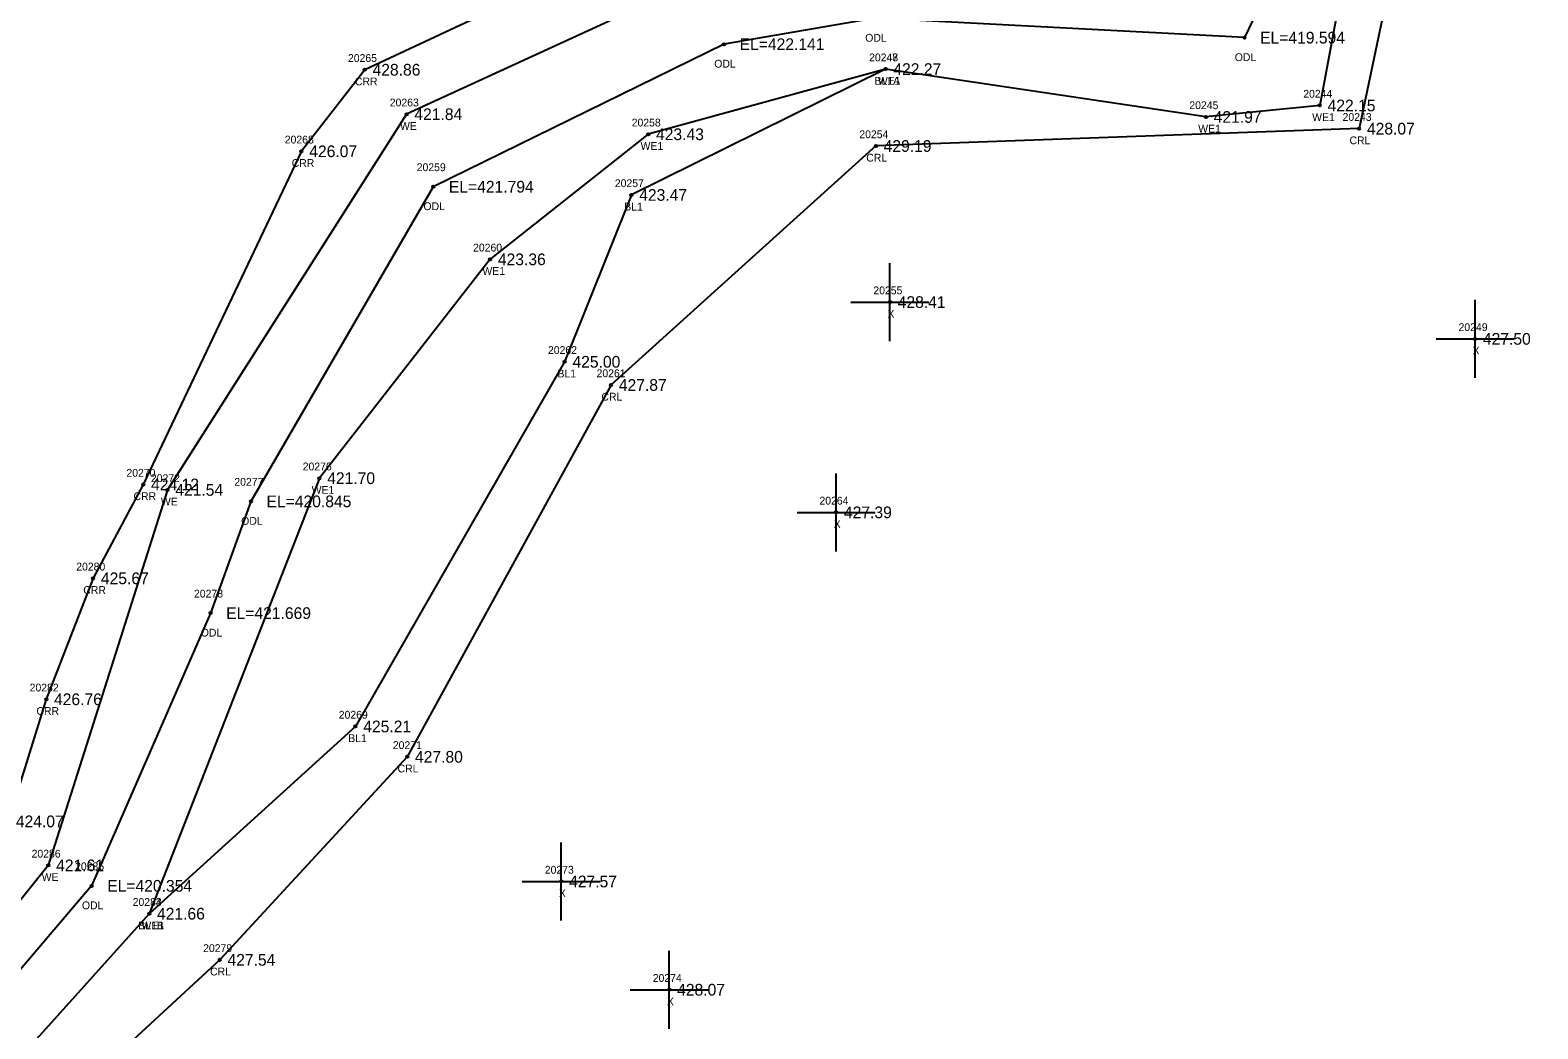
# Model space of a CAD drawing. Extents: x 1858461 to 1858936, y 1147060 to 1148183.
# Drawn here: x 1858716.7 to 1858909.9, y 1147619.9 to 1147747.9 of the extents above; entities that cross this region are included whole.
import ezdxf

# ---------------------------------------------------------------- set-up
doc = ezdxf.new("R2010")
doc.units = 0
for name, color, linetype in [('RD_DTM_BkLn1', 7, 'Continuous'), ('RD_DTM_BkLn_txCode', 7, 'Continuous'), ('RD_EX_H2O', 7, 'Continuous'), ('RD_EX_H2O_txCode', 7, 'Continuous'), ('RD_EX_Misc', 7, 'Continuous'), ('RD_EX_Misc_txCode', 7, 'Continuous'), ('RD_EX_TX_H2O_ELEV', 7, 'Continuous'), ('RD_EX_TX_Misc_ELEV', 7, 'Continuous'), ('RD_SMD_Locator', 7, 'Continuous')]:
    doc.layers.add(name, color=color, linetype=linetype)

msp = doc.modelspace()

# ---------------------------------------------------------------- linework, layer by layer
at = {"layer": 'RD_DTM_BkLn1'}
msp.add_lwpolyline([(1858826.32, 1147742.88), (1858793.75, 1147726.76), (1858785.2, 1147705.38), (1858758.39, 1147658.66), (1858731.96, 1147634.67)], dxfattribs=at)
at = {"layer": 'RD_EX_H2O'}
for points in [[(1858883.69, 1148147.48), (1858852.78, 1148112.64), (1858836.04, 1148037.73), (1858833.26, 1147975.2), (1858828.33, 1147910.84), (1858842, 1147848.22), (1858847.52, 1147794.04), (1858841.16, 1147786.48), (1858816.23, 1147769.28), (1858759.58, 1147742.8), (1858751.47, 1147732.35), (1858731.2, 1147689.66), (1858724.77, 1147677.64), (1858718.76, 1147662.14), (1858713.87, 1147646.5), (1858696.23, 1147629.99), (1858681.73, 1147631.9), (1858663.61, 1147613.98)], [(1858909.91, 1148115.72), (1858902.77, 1148116.75), (1858903.07, 1148125.04), (1858896.61, 1148132.76), (1858873.78, 1148129.33), (1858855.27, 1148111.83), (1858840.09, 1148036.93), (1858846.14, 1147982.36), (1858846.9, 1147967.54), (1858840.1, 1147928.32), (1858835.96, 1147922.3), (1858846.22, 1147851.69), (1858849.56, 1147834.44), (1858863.29, 1147789.22), (1858867.71, 1147772.35), (1858865.71, 1147761.59), (1858842.61, 1147761.06), (1858828.27, 1147754.21), (1858821.34, 1147763.04), (1858764.94, 1147737.1), (1858734.3, 1147688.97), (1858719.03, 1147640.86), (1858697.04, 1147613.49)], [(1858867.04, 1148108.26), (1858855.22, 1148032.48), (1858854.94, 1147976.71), (1858844.75, 1147924.02), (1858838.88, 1147914.94), (1858851.14, 1147854.11), (1858872.36, 1147792.48), (1858884.3, 1147779.68), (1858885.3, 1147773.97), (1858872.32, 1147746.91), (1858824.97, 1147749.39), (1858805.62, 1147746.07), (1858768.36, 1147727.81), (1858744.99, 1147687.5), (1858739.82, 1147673.18), (1858724.58, 1147638.24), (1858698.73, 1147607.87)], [(1858878.92, 1148104.66), (1858861.55, 1148027.41), (1858861.16, 1147976.95), (1858850.44, 1147924.2), (1858843.19, 1147917.77), (1858850.23, 1147884.47), (1858857.83, 1147857.85), (1858871.27, 1147824.7), (1858889.75, 1147780), (1858881.97, 1147738.22), (1858867.37, 1147736.75), (1858826.32, 1147742.88), (1858795.91, 1147734.53), (1858775.64, 1147718.51), (1858753.77, 1147690.47), (1858731.96, 1147634.67), (1858700.72, 1147599.99)], [(1858879.83, 1148102.54), (1858871.42, 1148034.27), (1858866.93, 1147971.73), (1858863.21, 1147909.44), (1858860.9, 1147860.04), (1858873.82, 1147825.54), (1858891.79, 1147781.55), (1858894.95, 1147773.07), (1858887.01, 1147735.25), (1858825.08, 1147733.03), (1858791.14, 1147702.41), (1858765.02, 1147654.77), (1858740.99, 1147628.76), (1858706.35, 1147596.83), (1858671.87, 1147580.02), (1858637.61, 1147560.56), (1858613.46, 1147539.88), (1858609.2, 1147499), (1858608.26, 1147474.71), (1858583.43, 1147442.99), (1858542.68, 1147417.32), (1858497.34, 1147430.55)]]:
    msp.add_lwpolyline(points, dxfattribs=at)
at = {"layer": 'RD_EX_Misc'}
for p, q in [((1858826.88, 1147708.03), (1858826.88, 1147718.03)), ((1858821.88, 1147713.03), (1858831.88, 1147713.03)), ((1858901.87, 1147703.32), (1858901.87, 1147713.32)), ((1858896.87, 1147708.32), (1858906.87, 1147708.32)), ((1858819.99, 1147681.09), (1858819.99, 1147691.09)), ((1858814.99, 1147686.09), (1858824.99, 1147686.09)), ((1858784.77, 1147633.8), (1858784.77, 1147643.8)), ((1858779.77, 1147638.8), (1858789.77, 1147638.8)), ((1858798.61, 1147619.93), (1858798.61, 1147629.93)), ((1858793.61, 1147624.93), (1858803.61, 1147624.93))]:
    msp.add_line(p, q, dxfattribs=at)
at = {"layer": 'RD_SMD_Locator'}
for centre in [(1858805.62, 1147746.07), (1858872.32, 1147746.91), (1858759.58, 1147742.8), (1858826.32, 1147742.88), (1858826.32, 1147742.88), (1858881.97, 1147738.22), (1858764.94, 1147737.1), (1858867.37, 1147736.75), (1858795.91, 1147734.53), (1858887.01, 1147735.25), (1858751.47, 1147732.35), (1858825.08, 1147733.03), (1858768.36, 1147727.81), (1858793.75, 1147726.76), (1858775.64, 1147718.51), (1858826.88, 1147713.03), (1858901.87, 1147708.32), (1858785.2, 1147705.38), (1858791.14, 1147702.41), (1858731.2, 1147689.66), (1858753.77, 1147690.47), (1858734.3, 1147688.97), (1858744.99, 1147687.5), (1858819.99, 1147686.09), (1858724.77, 1147677.64), (1858739.82, 1147673.18), (1858718.76, 1147662.14), (1858758.39, 1147658.66), (1858765.02, 1147654.77), (1858719.03, 1147640.86), (1858724.58, 1147638.24), (1858784.77, 1147638.8), (1858731.96, 1147634.67), (1858731.96, 1147634.67), (1858740.99, 1147628.76), (1858798.61, 1147624.93)]:
    msp.add_circle(centre, 0.15, dxfattribs=at)

# ---------------------------------------------------------------- texts
at = {"layer": 'RD_DTM_BkLn_txCode'}
for s, p in [('20248', (1858824.21, 1147743.88)), ('BL1A', (1858824.91, 1147740.88)), ('20257', (1858791.63, 1147727.76)), ('BL1', (1858792.83, 1147724.76)), ('20262', (1858783.06, 1147706.38)), ('BL1', (1858784.28, 1147703.38)), ('20269', (1858756.25, 1147659.66)), ('BL1', (1858757.47, 1147656.66)), ('20284', (1858729.84, 1147635.67)), ('BL1B', (1858730.56, 1147632.67))]:
    msp.add_text(s, height=1, dxfattribs=at).set_placement(p)
at = {"layer": 'RD_EX_H2O_txCode'}
for s, p in [('ODL', (1858823.72, 1147746.39)), ('20265', (1858757.43, 1147743.8)), ('ODL', (1858804.37, 1147743.07)), ('20247', (1858824.21, 1147743.88)), ('ODL', (1858871.07, 1147743.91)), ('CRR', (1858758.32, 1147740.8)), ('WE1', (1858825.34, 1147740.88)), ('20244', (1858879.85, 1147739.22)), ('20263', (1858762.79, 1147738.1)), ('20245', (1858865.25, 1147737.75)), ('20258', (1858793.79, 1147735.53)), ('WE1', (1858880.99, 1147736.22)), ('20243', (1858884.89, 1147736.25)), ('20268', (1858749.33, 1147733.35)), ('WE', (1858764.1, 1147735.1)), ('20254', (1858822.96, 1147734.03)), ('WE1', (1858866.39, 1147734.75)), ('CRL', (1858885.78, 1147733.25)), ('WE1', (1858794.93, 1147732.53)), ('CRR', (1858750.22, 1147730.35)), ('20259', (1858766.24, 1147729.81)), ('CRL', (1858823.85, 1147731.03)), ('ODL', (1858767.11, 1147724.81)), ('20260', (1858773.46, 1147719.51)), ('WE1', (1858774.66, 1147716.51)), ('20261', (1858789.29, 1147703.41)), ('CRL', (1858789.92, 1147700.41)), ('20276', (1858751.63, 1147691.47)), ('20270', (1858729.04, 1147690.66)), ('20272', (1858732.18, 1147689.97)), ('20277', (1858742.87, 1147689.5)), ('CRR', (1858729.95, 1147687.66)), ('WE', (1858733.46, 1147686.97)), ('WE1', (1858752.78, 1147688.47)), ('ODL', (1858743.75, 1147684.5)), ('20280', (1858722.61, 1147678.64)), ('CRR', (1858723.51, 1147675.64)), ('20278', (1858737.7, 1147675.18)), ('ODL', (1858738.57, 1147670.18)), ('20282', (1858716.64, 1147663.14)), ('CRR', (1858717.51, 1147660.14)), ('20271', (1858763.18, 1147655.77)), ('CRL', (1858763.79, 1147652.77)), ('20286', (1858716.89, 1147641.86)), ('WE', (1858718.19, 1147638.86)), ('20285', (1858722.46, 1147640.24)), ('ODL', (1858723.34, 1147635.24)), ('20283', (1858729.84, 1147635.67)), ('WE1', (1858730.97, 1147632.67)), ('20279', (1858738.87, 1147629.76)), ('CRL', (1858739.76, 1147626.76))]:
    msp.add_text(s, height=1, dxfattribs=at).set_placement(p)
at = {"layer": 'RD_EX_Misc_txCode'}
for s, p in [('20255', (1858824.76, 1147714.03)), ('X', (1858826.57, 1147711.03)), ('20249', (1858899.75, 1147709.32)), ('X', (1858901.55, 1147706.32)), ('20264', (1858817.85, 1147687.09)), ('X', (1858819.68, 1147684.09)), ('20273', (1858782.65, 1147639.8)), ('X', (1858784.46, 1147636.8)), ('20274', (1858796.49, 1147625.93)), ('X', (1858798.3, 1147622.93))]:
    msp.add_text(s, height=1, dxfattribs=at).set_placement(p)
at = {"layer": 'RD_EX_TX_H2O_ELEV'}
for s, p in [('EL=422.141', (1858807.62, 1147745.32)), ('EL=419.594', (1858874.32, 1147746.16)), ('428.86', (1858760.58, 1147742.05)), ('422.27', (1858827.32, 1147742.13)), ('422.15', (1858882.97, 1147737.47)), ('421.84', (1858765.94, 1147736.35)), ('421.97', (1858868.37, 1147736)), ('423.43', (1858796.91, 1147733.78)), ('428.07', (1858888.01, 1147734.5)), ('426.07', (1858752.47, 1147731.6)), ('429.19', (1858826.08, 1147732.28)), ('EL=421.794', (1858770.36, 1147727.06)), ('423.36', (1858776.64, 1147717.76)), ('427.87', (1858792.14, 1147701.66)), ('424.12', (1858732.2, 1147688.91)), ('421.70', (1858754.77, 1147689.72)), ('421.54', (1858735.3, 1147688.22)), ('EL=420.845', (1858746.99, 1147686.75)), ('425.67', (1858725.77, 1147676.89)), ('EL=421.669', (1858741.82, 1147672.43)), ('426.76', (1858719.76, 1147661.39)), ('427.80', (1858766.02, 1147654.02)), ('424.07', (1858714.87, 1147645.75)), ('421.61', (1858720.03, 1147640.11)), ('EL=420.354', (1858726.58, 1147637.49)), ('421.66', (1858732.96, 1147633.92)), ('427.54', (1858741.99, 1147628.01))]:
    msp.add_text(s, height=1.5, dxfattribs=at).set_placement(p)
at = {"layer": 'RD_EX_TX_Misc_ELEV'}
for s, p in [('422.27', (1858827.32, 1147742.13)), ('423.47', (1858794.75, 1147726.01)), ('428.41', (1858827.88, 1147712.28)), ('427.50', (1858902.87, 1147707.57)), ('425.00', (1858786.2, 1147704.63)), ('427.39', (1858820.99, 1147685.34)), ('425.21', (1858759.39, 1147657.91)), ('427.57', (1858785.77, 1147638.05)), ('421.66', (1858732.96, 1147633.92)), ('428.07', (1858799.61, 1147624.18))]:
    msp.add_text(s, height=1.5, dxfattribs=at).set_placement(p)

doc.saveas('drawing.dxf')
